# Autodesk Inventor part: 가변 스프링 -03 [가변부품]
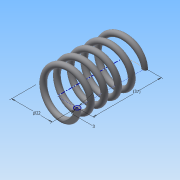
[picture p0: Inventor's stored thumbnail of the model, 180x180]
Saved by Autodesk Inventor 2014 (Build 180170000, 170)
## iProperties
Created: 2015-09
Part Number: 가변 스프링 -03 [가변부품]
Material: 강철, 탄소
Document SubType Name: Modeling
Designer: study
Density: 7.87 g/cm^3
Appearance: 반연마
Mass: 18.7691 g
Surface Area: 32.4279 cm^2
Volume: 2.3849 cm^3
Author: study
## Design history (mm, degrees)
sketch "스케치1"
  geometry: L1 (0, 0)-(11, 0); L2 (11, 0)-(11, 28.893); L3 (11, 28.893)-(0, 28.893); L4 (0, 28.893)-(0, 0); C1 r 1.5 at (11, 0)
  constraints: 8 end point, 2 parallel, 1 centre point, 1 coincident, 1 horizontal, 1 perpendicular
  dimensions: "d0" = 3 diameter of C1; "d1" = 22 diameter of L2 L4; "d2" = 28.89259 distance of L1.end L2.end (derived)
feature "코일1" pitch "d3" = 10; turns "d5" = 5; dims "d4" = 28.89259 (= d2), "d6" = 0, angle "d7" = 90 deg, angle "d8" = 90 deg, "d9" = 0, "d10" = 0
node "작업 평면1"
sketch "스케치2"
  geometry: L1 (-12.5, 0)-(-9.5, 0) reference; L2 (-12.5, 0)-(-9.5, 0) reference; 1 further point
  constraints: 2 horizontal alignment
extrude "돌출1" cut sketch "스케치2" stored distance "d12" = 10; taper "d13" = 0 deg
node "작업 평면2"
sketch "스케치3"
  geometry: L1 (-9.5, 0)-(-12.5, 0) reference; 1 further point
  constraints: 1 horizontal alignment
extrude "돌출2" cut sketch "스케치3" stored distance "d15" = 10; taper "d16" = 0 deg
node "솔리드1"
node "절단 모서리 투영1"
node "절단 모서리 투영2"
node "절단 모서리 투영3"
other parameters: "d11" = 0, "d14" = 28.89259 (= d2)
